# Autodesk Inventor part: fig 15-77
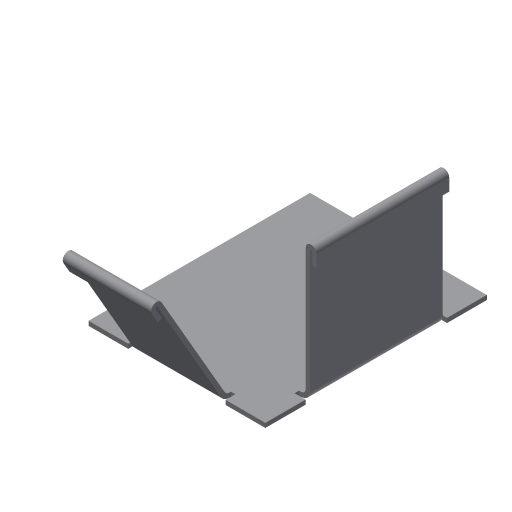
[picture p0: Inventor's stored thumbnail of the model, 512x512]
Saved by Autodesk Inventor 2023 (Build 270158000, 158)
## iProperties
Created: 2002-04
Part Number: fig 15-77
Document SubType Name: Sheet Metal
Density: 1 g/cm^3
Sheet Metal Rule: Default
Material: Generic
Appearance: Default
Control State: 0
Master: False
Checked Out: False
Shininess: 77.0
Angle Display Precision: 2
Document Length Units: 11269
Document Angle Units: 11279
Document Time Units: 11290
Document Mass Units: 11283
Document Length Units Precision: 3
Document Angle Units Precision: 2
Compacted: True
Density: 0.0
Volumn: 0.0
Area: 0.0
PropertySet Name: Model Information
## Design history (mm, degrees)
node "Face1"
  sketch "Sketch1"
    geometry: L1 (-17.882, 11.882)-(2.118, 11.882); L2 (2.118, 11.882)-(2.118, -13.176); L3 (2.118, -13.176)-(-17.882, -13.176); L4 (-17.882, -13.176)-(-17.882, 11.882)
    constraints: 8 end point, 2 parallel, 1 horizontal, 1 perpendicular
    dimensions: "d17" = 20 distance of L2.end L3.end
node "Flange2"
node "Flange3"
feature "Hem8" dims "d82" = 0.5 (= BendReliefWidth), "d83" = 0.25 (= BendReliefDepth), "d84" = 1 (= MinimumRemnant), "d85" = 0.5 (= BendRadius), "d86" = 2 (= 4 x Thickness), "d87" = 0.25 (= 0.5 x Thickness), "d88" = 0.125 (= 0.5 x d87), "d96" = 0.5 (= Thickness), "SeamGap" = 0.01
feature "Hem9" dims "d89" = 0.5 (= BendReliefWidth), "d90" = 0.25 (= BendReliefDepth), "d91" = 1 (= MinimumRemnant), "d92" = 0.5 (= BendRadius), "d93" = 2 (= 4 x Thickness), "d94" = 0.25 (= 0.5 x Thickness), "d95" = 0.125 (= 0.5 x d94), "d96" = 0.5 (= Thickness), "SeamGap" = 0.01
body "Solid1"
face "Plate1" dims "d96" = 0.5 (= Thickness)
sketch "Sketch3"
  geometry: L1 (5, 0)-(20, 0); L2 (20, 0)-(20, 15); L3 (20, 15)-(5, 15); L4 (5, 15)-(5, 0)
  constraints: 8 end point
face "Plate3" dims "d6" = 15, "d7" = 90 deg, "d8" = 0.5 (= BendRadius), "d18" = 5, "d19" = 15, "d96" = 0.5 (= Thickness), "MinimumRemnant" = 1 (= 2 x Thickness), "BendReliefWidth" = 0.5 (= Thickness)
bend "Bend2" dims "d6" = 15, "d7" = 90 deg, "d8" = 0.5 (= BendRadius), "d56" = 0.5 (= BendReliefWidth), "d57" = 0.25 (= BendReliefDepth), "d58" = 1 (= MinimumRemnant), "d96" = 0.5 (= Thickness), "SeamGap" = 0.01, "MinimumRemnant" = 1 (= 2 x Thickness), "BendReliefWidth" = 0.5 (= Thickness), "TransitionRadius" = 0.5 (= BendRadius)
sketch "Sketch6"
  geometry: L1 (15, 0)-(5, 0); L2 (5, 0)-(5, 15); L3 (5, 15)-(15, 15); L4 (15, 15)-(15, 0)
  constraints: 8 end point
face "Plate4" dims "d20" = 5, "d21" = 10, "d23" = 15, "d24" = 60 deg, "d25" = 0.5 (= BendRadius), "d96" = 0.5 (= Thickness), "MinimumRemnant" = 1 (= 2 x Thickness), "BendReliefWidth" = 0.5 (= Thickness)
bend "Bend3" dims "d22" = 0.5 (= BendRadius), "d23" = 15, "d24" = 60 deg, "d25" = 0.5 (= BendRadius), "d59" = 0.5 (= BendReliefWidth), "d60" = 0.25 (= BendReliefDepth), "d61" = 1 (= MinimumRemnant), "d96" = 0.5 (= Thickness), "SeamGap" = 0.01, "MinimumRemnant" = 1 (= 2 x Thickness), "BendReliefWidth" = 0.5 (= Thickness)
sketch "Sketch12"
  geometry: L1 (0.433, 0.25)-(0, 0); L2 (-0.217, -0.125)-(0.471, -1.316); L3 (0.471, -1.316)-(0.038, -1.566); L4 (0.038, -1.566)-(-0.65, -0.375); A1 r 0.125 centre (-0.108, -0.063) between (0, 0) and (-0.217, -0.125); A2 r 0.625 centre (-0.108, -0.063) between (0.433, 0.25) and (-0.65, -0.375)
  constraints: 8 end point, 4 point on circle
sketch "Sketch13"
  geometry: L1 (0.5, 0)-(0, 0); L2 (-0.25, 0)-(-0.25, -1.375); L3 (-0.25, -1.375)-(-0.75, -1.375); L4 (-0.75, -1.375)-(-0.75, 0); A1 r 0.125 centre (-0.125, 0) between (0, 0) and (-0.25, 0); A2 r 0.625 centre (-0.125, 0) between (0.5, 0) and (-0.75, 0)
  constraints: 8 end point, 4 point on circle
other parameters: "Thickness" = 0.5, "BendRadius" = 0.5 (= Thickness), "BendReliefDepth" = 0.25 (= 0.5 x Thickness), "CornerReliefSize" = 2 (= 4 x Thickness), "d0" = 0.5 (= BendRadius), "d5" = 0.5 (= BendRadius), "d26" = 0.5 (= BendRadius), "d30" = 0.5 (= BendRadius), "JacobiRadiusSize" = 0.5 (= Thickness), "GapSize" = 0.5 (= Thickness)
